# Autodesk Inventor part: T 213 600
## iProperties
Created: 2005-10
Part Number: T 213 600
Material: Durethan BKV30H
Document SubType Name: Modeling
Designer: I.Baliuc
Manufacturer: Standard
Standards Organization: Custom
Description: Isolator
Density: 0.94 g/cm^3
Title: Isolator
Company: Mayer & Müller AG Schaltgeräte
Author: T.Messerschmitt
Revision Number: 213600
Keywords: 213549
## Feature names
1. Extrusion2
2. Extrusion3
3. Extrusion4
4. Extrusion5
5. Extrusion6
6. Spiegeln1 [Mirror]
7. Rundung3 [Fillet]
8. Rundung4 [Fillet]
9. Extrusion7
10. Bohrung1 [Hole]
11. Bohrung2 [Hole]
